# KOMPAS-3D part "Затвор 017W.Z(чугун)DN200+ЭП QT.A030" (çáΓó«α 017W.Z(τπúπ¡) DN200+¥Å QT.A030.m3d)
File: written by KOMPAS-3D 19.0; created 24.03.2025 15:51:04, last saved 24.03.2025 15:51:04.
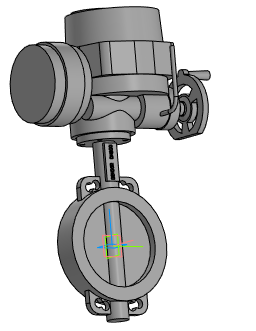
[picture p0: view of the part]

Document properties: Полное имя файла: Затвор 017W.Z(чугун) DN200+ЭП QT.A030.a3d

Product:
- Part/product: Затвор 017W.Z(чугун)DN200+ЭП QT.A030
    Масса: 135.15

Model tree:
1. Операция без истории:1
